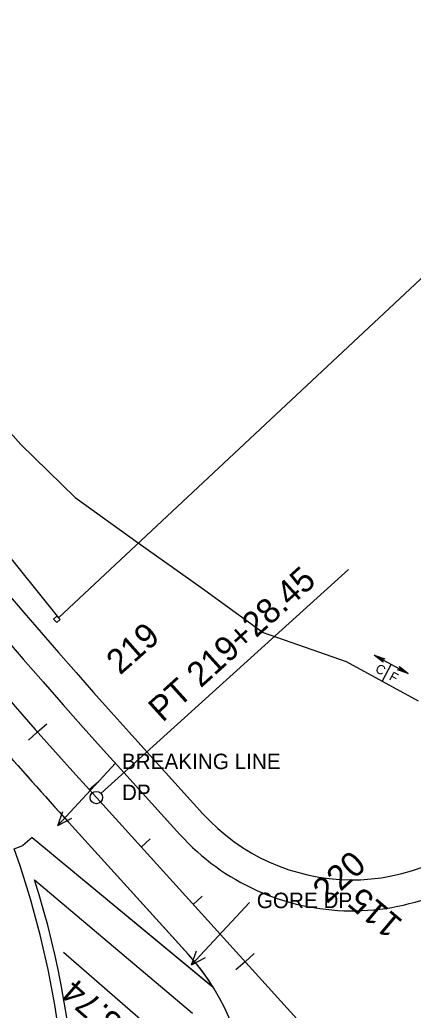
# Model space of a CAD drawing. Extents: x 2717836 to 2719883, y 337327 to 339806.
# Drawn here: x 2718977.8 to 2719104.8, y 338088.2 to 338408.2 of the extents above; entities that cross this region are included whole.
import ezdxf

# ---------------------------------------------------------------- set-up
doc = ezdxf.new("R2010")
doc.units = 0
for name, color, linetype in [('Level 1', 7, 'Continuous'), ('Level 2', 7, 'Continuous'), ('Level 22', 7, 'Continuous'), ('Level 23', 7, 'Continuous'), ('Level 3', 7, 'Continuous'), ('Level 31', 7, 'Continuous'), ('Level 52', 7, 'Continuous'), ('Level 6', 7, 'Continuous'), ('Level 60', 7, 'Continuous'), ('Level 61', 7, 'Continuous'), ('Level 8', 7, 'Continuous')]:
    doc.layers.add(name, color=color, linetype=linetype)

msp = doc.modelspace()

# ---------------------------------------------------------------- linework, layer by layer
at = {"layer": 'Level 1'}
msp.add_line((2719002.47, 338156.9), (2719189.33, 337950.54), dxfattribs=at)
for centre, radius, start, end in [((2715303.11, 341318.59), 5000, 318.95467, 328.67948), ((2720744.45, 339734.24), 2350, 206.79977, 222.16044)]:
    msp.add_arc(centre, radius, start, end, dxfattribs=at)
at = {"layer": 'Level 2'}
for centre, radius, start, end in [((2718692.92, 338040.11), 300.27, 344.2175, 19.5026), ((2718976.55, 338055.91), 75, 318.8661, 42.1604)]:
    msp.add_arc(centre, radius, start, end, dxfattribs=at)
at = {"layer": 'Level 22'}
for p, q in [((2718961.78, 338289.18), (2718978.1, 338271)), ((2718978.1, 338271), (2718995.61, 338253.86)), ((2718995.61, 338253.86), (2719015.92, 338239.2)), ((2719015.92, 338239.2), (2719036.37, 338224.82)), ((2719036.37, 338224.82), (2719056.38, 338210.21)), ((2719056.38, 338210.21), (2719083.16, 338200.89)), ((2719083.16, 338200.89), (2719094.77, 338194.54)), ((2719094.77, 338194.54), (2719106.38, 338188.19))]:
    msp.add_line(p, q, dxfattribs=at)
at = {"layer": 'Level 23'}
for p in [(2719374.17, 338574.5), (2718939.3, 338278.13)]:
    msp.add_line(p, (2718990.26, 338215.01), dxfattribs=at)
msp.add_lwpolyline([(2718989.7, 338213.43), (2718988.66, 338214.51), (2718989.74, 338215.55), (2718990.78, 338214.47)], close=True, dxfattribs=at)
at = {"layer": 'Level 3'}
for p, q in [((2719011.37, 338164.95), (2719029.47, 338144.96)), ((2718993.58, 338148.84), (2719031.25, 338107.23)), ((2718981.73, 338144.04), (2718978.77, 338141.36)), ((2718981.73, 338144.04), (2719039.16, 338096.51)), ((2718975.96, 338140.35), (2718978.77, 338141.36)), ((2719031.25, 338107.23), (2719032.14, 338106.25)), ((2719039.16, 338096.51), (2719040.11, 338095.72))]:
    msp.add_line(p, q, dxfattribs=at)
for centre, radius, start, end in [((2720744.45, 339734.24), 2338, 206.79977, 222.16044), ((2720759.57, 339747.51), 2382.12, 220.43651, 222.14825), ((2721152.65, 340103.72), 2912.58, 222.15462, 222.1586), ((2719085.06, 338195.3), 75, 222.1604, 316.7247)]:
    msp.add_arc(centre, radius, start, end, dxfattribs=at)
at = {"layer": 'Level 31'}
for p, q in [((2719003.96, 338158.24), (2719083.85, 338230.58)), ((2718983.5, 338178.1), (2718986.5, 338180.75)), ((2718983.5, 338178.1), (2718980.51, 338175.45)), ((2719000.16, 338159.46), (2719003.13, 338162.14)), ((2719016.94, 338140.92), (2719019.9, 338143.61)), ((2719033.72, 338122.39), (2719036.68, 338125.08)), ((2719072.55, 338036.63), (2718991.88, 338106.86)), ((2719050.5, 338103.86), (2719053.46, 338106.55)), ((2719050.5, 338103.86), (2719047.53, 338101.18))]:
    msp.add_line(p, q, dxfattribs=at)
msp.add_circle((2719002.47, 338156.9), 2, dxfattribs=at)
at = {"layer": 'Level 52'}
for p, q in [((2719092.24, 338202.95), (2719103.21, 338196.95)), ((2719097.73, 338199.95), (2719094.77, 338194.54))]:
    msp.add_line(p, q, dxfattribs=at)
for points in [[(2719092.24, 338202.95), (2719095.69, 338201.75), (2719094.61, 338201.65), (2719095.1, 338200.67)], [(2719103.21, 338196.95), (2719099.76, 338198.15), (2719100.84, 338198.25), (2719100.35, 338199.23)]]:
    msp.add_lwpolyline(points, close=True, dxfattribs=at)
at = {"layer": 'Level 6'}
for p, q in [((2719018.78, 338171.66), (2719036.88, 338151.67)), ((2718982.51, 338130.31), (2719033.5, 338087.25))]:
    msp.add_line(p, q, dxfattribs=at)
for centre, radius, start, end in [((2720744.45, 339734.24), 2328, 208.64257, 222.16044), ((2719085.06, 338195.3), 65, 222.1604, 316.7247), ((2718697.4, 338040.25), 299, 346.4135, 17.5292)]:
    msp.add_arc(centre, radius, start, end, dxfattribs=at)
at = {"layer": 'Level 60'}
for p, q in [((2719051.89, 338122.96), (2719033.23, 338102.85)), ((2719033.23, 338102.85), (2719034.86, 338107.38)), ((2719033.23, 338102.85), (2719037.76, 338105.2))]:
    msp.add_line(p, q, dxfattribs=at)
at = {"layer": 'Level 61'}
for p, q in [((2719008.7, 338167.99), (2718990.04, 338147.88)), ((2718990.04, 338147.88), (2718991.67, 338152.41)), ((2718990.04, 338147.88), (2718994.57, 338150.23))]:
    msp.add_line(p, q, dxfattribs=at)
at = {"layer": 'Level 8'}
for p, q in [((2718993.58, 338148.84), (2719032.14, 338106.25)), ((2718981.73, 338144.04), (2718978.77, 338141.36)), ((2718981.73, 338144.04), (2719040.05, 338095.77)), ((2718975.96, 338140.35), (2718978.77, 338141.36))]:
    msp.add_line(p, q, dxfattribs=at)
for centre, radius, start, end in [((2720744.45, 339734.24), 2362, 220.42917, 222.16044), ((2718976.55, 338055.91), 75, 32.502, 42.1604)]:
    msp.add_arc(centre, radius, start, end, dxfattribs=at)

# ---------------------------------------------------------------- texts
at = {"layer": 'Level 31'}
for s, rotation, p in [('PT 219+28.45', 42.1604, (2719023.84, 338180.97)), ('219', 41.4667, (2719010.13, 338196.29)), ('220', 42.1604, (2719076.9, 338122.37)), ('115', 139.8286, (2719101.83, 338116.91)), ('PC 114+23.74', 138.9547, (2719047.63, 338053.69))]:
    msp.add_text(s, height=8, rotation=rotation, dxfattribs=at).set_placement(p)
at = {"layer": 'Level 52'}
for s, p in [('C', (2719092.28, 338197.66)), ('F', (2719096.77, 338195.13))]:
    msp.add_text(s, height=3, rotation=331.3352, dxfattribs=at).set_placement(p)
at = {"layer": 'Level 60'}
msp.add_text('GORE DP', height=5, dxfattribs=at).set_placement((2719054.28, 338121.17))
at = {"layer": 'Level 61'}
for s, p in [('BREAKING LINE ', (2719010.72, 338166.08)), ('DP', (2719010.72, 338156.08))]:
    msp.add_text(s, height=5, dxfattribs=at).set_placement(p)

doc.saveas('drawing.dxf')
